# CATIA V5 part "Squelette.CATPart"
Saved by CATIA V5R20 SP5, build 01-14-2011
Part number: Squelette
Publications: "Plan Dessous", "plan profil", "A", "B", "C", "D", "Point.7", "Point.9", "Droite.1", "Point.10", "Point.11", "Droite.2", "Point.12", "Droite.3", "plan coulisseau transversal"
Bounding box of the stored display mesh (mm): x 0 to 20, y 0 to 305.571, z -8.409 to 152.774
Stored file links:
  F:\iao fini\Squelette.CATPart
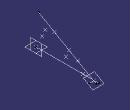
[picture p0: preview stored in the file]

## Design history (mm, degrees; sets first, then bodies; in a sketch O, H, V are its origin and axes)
Set1 "set géométrique"
  Plane1 "Plan Dessous": type Offset, RefPlane xy-plane, Offset 0
  Plane2 "plan profil": type Offset, RefPlane yz-plane, Offset 0
  Point1 "A": type OnPlane, Support Plane2, H 29.362, V 59.687, Direction (0, 1, 0)
  Point2 "B": type OnPlane, Support Plane2, H 44.192, V 94.318, Direction (0, 1, 0)
  Point3 "C": type OnPlane, Support Plane2, H 162.215, V 66.933, Direction (0, 1, 0)
  Point4 "D": type OnPlane, Support Plane2, H 147.483, V 32.022, Direction (0, 1, 0)
  Point5: type OnPlane, Support Plane2, H 90.556, V 108.035, Direction (0, 1, 0)
  Point6: type OnPlane, Support Plane2, H 203.571, V 43.289, Direction (0, 1, 0)
  Line1: type PtPt, FirstPoint Point5, SecondPoint Point6, Support Plane2, Start 90, End 104
  Point7: type OnPlane, Support Plane2, H 0, V 0, Direction (0, 1, 0)
  Point8: type OnPlane, Support Plane2, H 230.571, V 0.804, Direction (0, 1, 0)
  Line2: type PtPt, FirstPoint Point7, SecondPoint Point8, Support Plane2, End 75
  Point9: type OnCurve, Support Line1, Length 311.141
  Line3: type Normal, RefPoint Point9, RefSkin Plane2, Start 0, End 20
  Plane3 "plan coulisseau transversal": type Angle, RefPlane Plane1, Direction Line3, Angle -30
Body1 (main body)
